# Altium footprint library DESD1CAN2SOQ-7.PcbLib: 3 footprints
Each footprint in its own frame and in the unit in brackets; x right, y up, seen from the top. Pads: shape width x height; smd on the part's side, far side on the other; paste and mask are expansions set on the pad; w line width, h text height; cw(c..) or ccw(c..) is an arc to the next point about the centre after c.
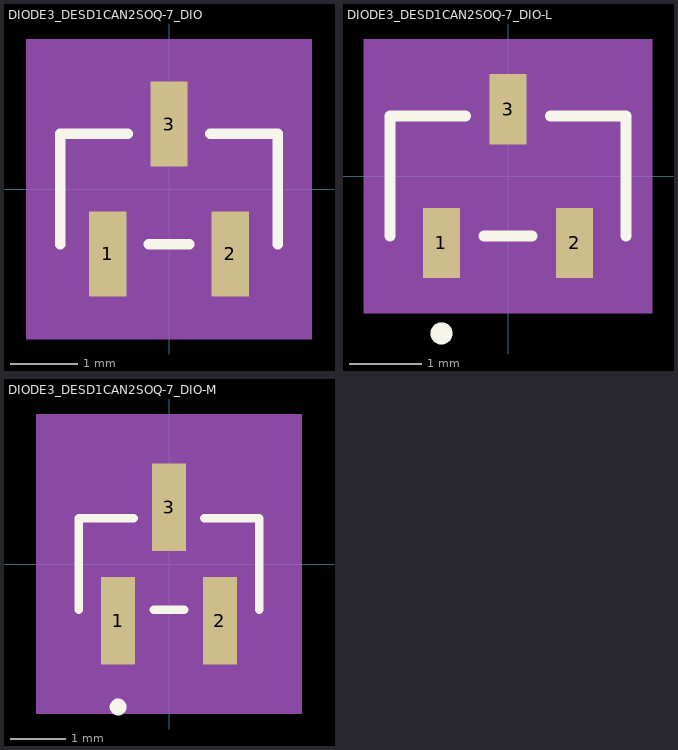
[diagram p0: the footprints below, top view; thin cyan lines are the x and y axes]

## DIODE3_DESD1CAN2SOQ-7_DIO [mil]
pads (3):
  rect 22x50 smd paste+0 mask+0: 1(-36.02,-38.21) 2(36.02,-38.21) 3(0,38.21)
Top Overlay:
  lines w6: -64,-32.5 -64,32.5 -24.1,32.5 ; -11.92,-32.5 11.92,-32.5 ; 24.1,32.5 64,32.5 64,-32.5
Mechanical 5:
  region: -84,88.21 84,88.21 84,-88.21 -84,-88.21
Mechanical 13:
  circle w0: c-36.02,-17.5 r0
  lines w1: -59,-27.5 59,-27.5 59,27.5 -59,27.5 -59,-27.5 ; -46.02,-49.21 -46.02,-27.5 -26.02,-27.5 -26.02,-49.21 -46.02,-49.21 ; -10,27.5 10,27.5 10,49.21 -10,49.21 -10,27.5 ; 26.02,-49.21 26.02,-27.5 46.02,-27.5 46.02,-49.21 26.02,-49.21
Mechanical 15:
  region: -69,-37.5 -69,37.5 -20,37.5 -20,73.21 20,73.21 20,37.5 69,37.5 69,-37.5 56.02,-37.5 56.02,-73.21 -56.02,-73.21 -56.02,-37.5
  lines w6: -69,-37.5 -69,37.5 -20,37.5 -20,73.21 20,73.21 20,37.5 69,37.5 69,-37.5 56.02,-37.5 56.02,-73.21 -56.02,-73.21 -56.02,-37.5 -69,-37.5
3D body "DIODE3_DESD1CAN2SOQ-7_DIO.step": height 43.11, standoff 0, extent -59.02,-49.21 59.02,49.21

## DIODE3_DESD1CAN2SOQ-7_DIO-L [mil]
pads (3):
  rect 20x38 smd paste+0 mask+0: 1(-36.02,-36.21) 2(36.02,-36.21) 3(0,36.21)
Top Overlay:
  circle w6: c-36.02,-85.21 r3
  lines w6: -64,-32.5 -64,32.5 -23.1,32.5 ; -12.92,-32.5 12.92,-32.5 ; 23.1,32.5 64,32.5 64,-32.5
Mechanical 5:
  region: -78,74.21 78,74.21 78,-74.21 -78,-74.21
Mechanical 13:
  circle w0: c-36.02,-17.5 r3
  lines w1: -59,-27.5 59,-27.5 59,27.5 -59,27.5 -59,-27.5 ; -46.02,-49.21 -46.02,-27.5 -26.02,-27.5 -26.02,-49.21 -46.02,-49.21 ; -10,27.5 10,27.5 10,49.21 -10,49.21 -10,27.5 ; 26.02,-49.21 26.02,-27.5 46.02,-27.5 46.02,-49.21 26.02,-49.21
Mechanical 15:
  region: -63,-31.5 -63,31.5 -14,31.5 -14,59.21 14,59.21 14,31.5 63,31.5 63,-31.5 50.02,-31.5 50.02,-59.21 -50.02,-59.21 -50.02,-31.5
  lines w6: -63,-31.5 -63,31.5 -14,31.5 -14,59.21 14,59.21 14,31.5 63,31.5 63,-31.5 50.02,-31.5 50.02,-59.21 -50.02,-59.21 -50.02,-31.5 -63,-31.5
3D body "DIODE3_DESD1CAN2SOQ-7_DIO.step": height 43.11, standoff 0, extent -59.02,-49.21 59.02,49.21

## DIODE3_DESD1CAN2SOQ-7_DIO-M [mil]
pads (3):
  rect 24x62 smd paste+0 mask+0: 1(-36.02,-40.21) 2(36.02,-40.21) 3(0,40.21)
Top Overlay:
  circle w6: c-36.02,-101.21 r3
  lines w6: -64,-32.5 -64,32.5 -25.1,32.5 ; -10.92,-32.5 10.92,-32.5 ; 25.1,32.5 64,32.5 64,-32.5
Mechanical 5:
  region: -94,106.21 94,106.21 94,-106.21 -94,-106.21
Mechanical 13:
  circle w0: c-36.02,-17.5 r3
  lines w1: -59,-27.5 59,-27.5 59,27.5 -59,27.5 -59,-27.5 ; -46.02,-49.21 -46.02,-27.5 -26.02,-27.5 -26.02,-49.21 -46.02,-49.21 ; -10,27.5 10,27.5 10,49.21 -10,49.21 -10,27.5 ; 26.02,-49.21 26.02,-27.5 46.02,-27.5 46.02,-49.21 26.02,-49.21
Mechanical 15:
  region: -79,-47.5 -79,47.5 -30,47.5 -30,91.21 30,91.21 30,47.5 79,47.5 79,-47.5 66.02,-47.5 66.02,-91.21 -66.02,-91.21 -66.02,-47.5
  lines w6: -79,-47.5 -79,47.5 -30,47.5 -30,91.21 30,91.21 30,47.5 79,47.5 79,-47.5 66.02,-47.5 66.02,-91.21 -66.02,-91.21 -66.02,-47.5 -79,-47.5
3D body "DIODE3_DESD1CAN2SOQ-7_DIO.step": height 43.11, standoff 0, extent -59.02,-49.21 59.02,49.21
